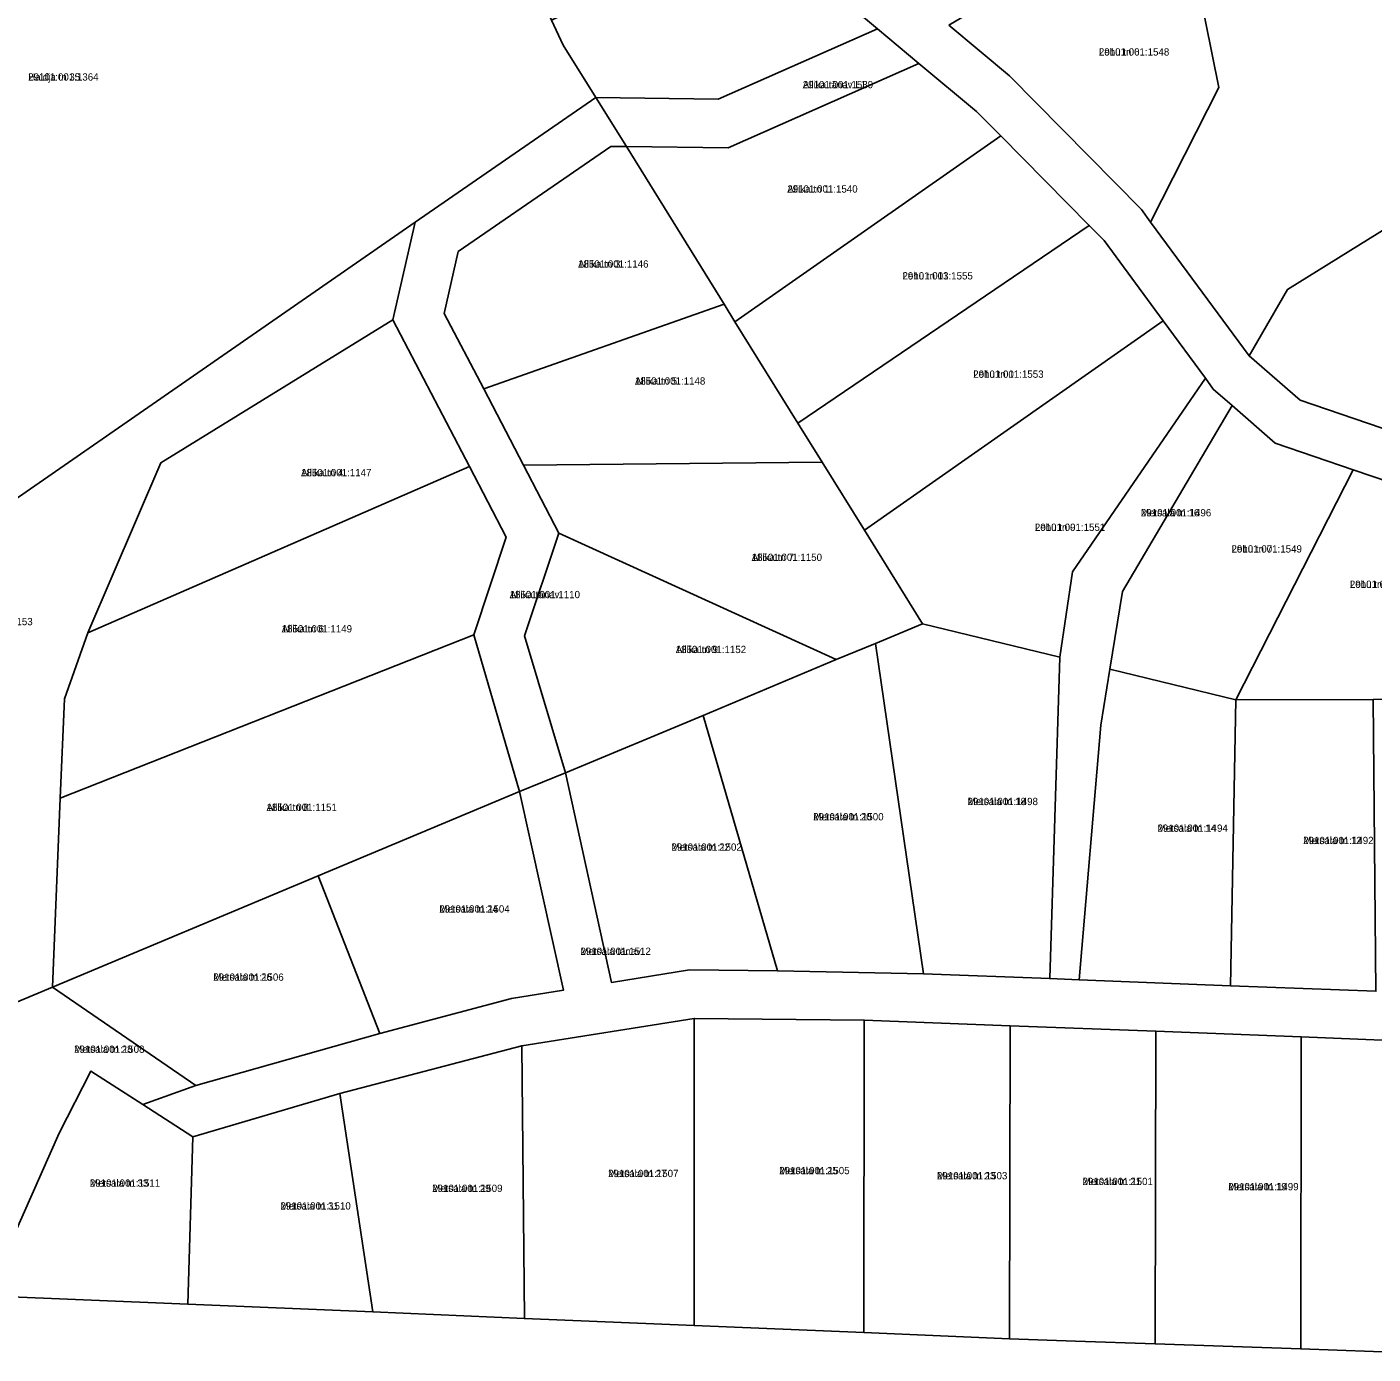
# Model space of a CAD drawing. Extents: x 660838 to 697091, y 6455678 to 6479886.
# Drawn here: x 664567.5 to 664844.9, y 6467484.5 to 6467758.1 of the extents above; entities that cross this region are included whole.
import ezdxf

# ---------------------------------------------------------------- set-up
doc = ezdxf.new("R2010")
doc.units = 0
for name, color, linetype in [('L_AADRESS', 7, 'Continuous'), ('PIIR', 7, 'Continuous'), ('TUNNUS', 7, 'Continuous')]:
    doc.layers.add(name, color=color, linetype=linetype)

msp = doc.modelspace()

# ---------------------------------------------------------------- linework, layer by layer
at = {"layer": 'PIIR'}
for points in [[(664619.34, 6467866.33), (664624.4, 6467868.22), (664630.66, 6467854.99), (664649.11, 6467815.91), (664657.57, 6467797.79), (664675.64, 6467759.51), (664678.05, 6467754.38), (664684.75, 6467743.56), (664647.54, 6467717.86), (664514.87, 6467625.93), (664481.41, 6467691.32), (664477.79, 6467698.39), (664474.15, 6467705.43), (664440.02, 6467772.59), (664457.91, 6467781.88), (664480.66, 6467793.7), (664503.48, 6467805.49), (664530.83, 6467819.65), (664552.51, 6467830.88), (664575.16, 6467842.71), (664617.32, 6467864.54)], [(664842.36, 6467851.27), (664867.78, 6467863.95), (664869.83, 6467846.19), (664877, 6467822.84), (664860.47, 6467801.99), (664847.14, 6467779.64), (664853.5, 6467754.14), (664860.79, 6467724.82), (664827.31, 6467704.02), (664819.37, 6467690.3), (664799.08, 6467717.91), (664813.14, 6467745.61), (664804.89, 6467786.54), (664808.03, 6467816.03), (664815.87, 6467838.1)], [(664757.47, 6467758.52), (664804.89, 6467786.54), (664813.14, 6467745.61), (664799.08, 6467717.91), (664797.22, 6467720.47), (664770, 6467748.08)], [(664675.64, 6467759.51), (664715.03, 6467778.23), (664735.74, 6467763.68), (664742.76, 6467757.76), (664709.94, 6467743.24), (664684.75, 6467743.56), (664678.05, 6467754.38)], [(664709.94, 6467743.24), (664742.76, 6467757.76), (664751.34, 6467750.6), (664711.99, 6467733.21), (664691.05, 6467733.46), (664684.75, 6467743.56)], [(664711.99, 6467733.21), (664751.34, 6467750.6), (664763.2, 6467740.7), (664768.19, 6467735.68), (664713.42, 6467697.35), (664711.2, 6467700.98), (664691.05, 6467733.46)], [(664647.54, 6467717.86), (664684.75, 6467743.56), (664691.05, 6467733.46), (664687.83, 6467733.51), (664656.41, 6467711.8), (664653.51, 6467699.08), (664661.64, 6467683.5), (664669.82, 6467667.8), (664677.15, 6467653.76), (664670.07, 6467632.61), (664678.48, 6467604.32), (664669.05, 6467600.48), (664659.59, 6467632.77), (664666.28, 6467652.95), (664658.71, 6467667.49), (664642.94, 6467697.77)], [(664713.42, 6467697.35), (664768.19, 6467735.68), (664786.42, 6467717.22), (664726.38, 6467676.47)], [(664656.41, 6467711.8), (664687.83, 6467733.51), (664691.05, 6467733.46), (664711.2, 6467700.98), (664661.64, 6467683.5), (664653.51, 6467699.08)], [(664829.88, 6467681.16), (664819.37, 6467690.3), (664827.31, 6467704.02), (664860.79, 6467724.82), (664875.61, 6467697.26), (664888.65, 6467672.94), (664889.91, 6467670.66), (664884.33, 6467671.17), (664887.16, 6467665.73), (664866.07, 6467668.81)], [(664514.87, 6467625.93), (664647.54, 6467717.86), (664642.94, 6467697.77), (664595.08, 6467668.29), (664580.08, 6467633.23), (664575.25, 6467619.58), (664574.4, 6467599.12), (664572.78, 6467560.2), (664552.54, 6467551.71)], [(664726.38, 6467676.47), (664786.42, 6467717.22), (664789.5, 6467714.09), (664801.63, 6467697.52), (664740.1, 6467654.38), (664731.4, 6467668.38)], [(664661.64, 6467683.5), (664711.2, 6467700.98), (664713.42, 6467697.35), (664726.38, 6467676.47), (664731.4, 6467668.38), (664669.82, 6467667.8)], [(664595.08, 6467668.29), (664642.94, 6467697.77), (664658.71, 6467667.49), (664580.08, 6467633.23)], [(664740.1, 6467654.38), (664801.63, 6467697.52), (664810.36, 6467685.72), (664783.01, 6467645.76), (664780.36, 6467628.21), (664752.07, 6467635.08)], [(664783.01, 6467645.76), (664810.36, 6467685.72), (664811.98, 6467683.48), (664815.86, 6467680.1), (664793.3, 6467641.76), (664790.69, 6467625.73), (664788.83, 6467614.18), (664784.37, 6467561.7), (664778.28, 6467561.92), (664780.36, 6467628.21)], [(664793.3, 6467641.76), (664815.86, 6467680.1), (664824.76, 6467672.34), (664840.82, 6467666.85), (664816.61, 6467619.42), (664790.69, 6467625.73)], [(664580.08, 6467633.23), (664658.71, 6467667.49), (664666.28, 6467652.95), (664659.59, 6467632.77), (664574.4, 6467599.12), (664575.25, 6467619.58)], [(664669.82, 6467667.8), (664731.4, 6467668.38), (664740.1, 6467654.38), (664752.07, 6467635.08), (664742.36, 6467631.01), (664734.26, 6467627.69), (664677.15, 6467653.76)], [(664816.61, 6467619.42), (664840.82, 6467666.85), (664863.68, 6467659.07), (664862.83, 6467619.55), (664844.92, 6467619.44)], [(664677.15, 6467653.76), (664734.26, 6467627.69), (664706.85, 6467616.2), (664678.48, 6467604.32), (664670.07, 6467632.61)], [(664742.36, 6467631.01), (664752.07, 6467635.08), (664780.36, 6467628.21), (664778.28, 6467561.92), (664752.25, 6467562.92)], [(664574.4, 6467599.12), (664659.59, 6467632.77), (664669.05, 6467600.48), (664627.51, 6467583.11), (664572.78, 6467560.2)], [(664734.26, 6467627.69), (664742.36, 6467631.01), (664752.25, 6467562.92), (664722.18, 6467563.54), (664706.85, 6467616.2)], [(664788.83, 6467614.18), (664790.69, 6467625.73), (664816.61, 6467619.42), (664815.52, 6467560.47), (664784.37, 6467561.7)], [(664815.52, 6467560.47), (664816.61, 6467619.42), (664844.92, 6467619.44), (664845.51, 6467559.31)], [(664687.95, 6467561.16), (664678.48, 6467604.32), (664706.85, 6467616.2), (664722.18, 6467563.54), (664704.03, 6467563.73)], [(664627.51, 6467583.11), (664669.05, 6467600.48), (664678.06, 6467559.53), (664667.34, 6467557.83), (664640.26, 6467550.63)], [(664572.78, 6467560.2), (664627.51, 6467583.11), (664640.26, 6467550.63), (664602.35, 6467539.87)], [(664552.54, 6467551.71), (664572.78, 6467560.2), (664602.35, 6467539.87), (664591.41, 6467535.98), (664580.7, 6467542.85), (664574.13, 6467530.09), (664559.27, 6467496.52), (664552.12, 6467496.78)], [(664669.53, 6467548.06), (664705.02, 6467553.73), (664705.02, 6467490.38), (664670.03, 6467491.84)], [(664705.02, 6467553.73), (664740.06, 6467553.37), (664740, 6467488.95), (664705.02, 6467490.38)], [(664740, 6467488.95), (664740.06, 6467553.37), (664770.11, 6467552.2), (664769.97, 6467487.69)], [(664770.11, 6467552.2), (664800.13, 6467551.07), (664800.01, 6467486.61), (664783.58, 6467487.15), (664769.97, 6467487.69)], [(664800.01, 6467486.61), (664800.13, 6467551.07), (664830.13, 6467549.9), (664830.01, 6467485.58)], [(664632, 6467538.25), (664669.53, 6467548.06), (664670.03, 6467491.84), (664638.82, 6467493.22)], [(664830.13, 6467549.9), (664860.11, 6467548.72), (664860, 6467484.52), (664830.01, 6467485.58)], [(664591.41, 6467535.98), (664601.69, 6467529.31), (664600.69, 6467494.8), (664559.27, 6467496.52), (664574.13, 6467530.09), (664580.7, 6467542.85)], [(664601.69, 6467529.31), (664632, 6467538.25), (664638.82, 6467493.22), (664600.69, 6467494.8)]]:
    msp.add_lwpolyline(points, close=True, dxfattribs=at)
for points in [[(664863.68, 6467659.07), (664840.82, 6467666.85), (664824.76, 6467672.34), (664815.86, 6467680.1), (664811.98, 6467683.48), (664810.36, 6467685.72), (664801.63, 6467697.52), (664789.5, 6467714.09), (664786.42, 6467717.22), (664768.19, 6467735.68), (664763.2, 6467740.7), (664751.34, 6467750.6), (664742.76, 6467757.76), (664735.74, 6467763.68)], [(664757.47, 6467758.52), (664770, 6467748.08), (664797.22, 6467720.47), (664799.08, 6467717.91), (664819.37, 6467690.3), (664829.88, 6467681.16), (664866.07, 6467668.81)], [(664860.11, 6467548.72), (664830.13, 6467549.9), (664800.13, 6467551.07), (664770.11, 6467552.2), (664740.06, 6467553.37), (664705.02, 6467553.73), (664669.53, 6467548.06), (664632, 6467538.25), (664601.69, 6467529.31), (664591.41, 6467535.98), (664602.35, 6467539.87), (664640.26, 6467550.63), (664667.34, 6467557.83), (664678.06, 6467559.53), (664669.05, 6467600.48), (664678.48, 6467604.32), (664687.95, 6467561.16), (664704.03, 6467563.73), (664722.18, 6467563.54), (664752.25, 6467562.92), (664778.28, 6467561.92), (664784.37, 6467561.7), (664815.52, 6467560.47), (664845.51, 6467559.31)], [(664559.27, 6467496.52), (664600.69, 6467494.8), (664638.82, 6467493.22), (664670.03, 6467491.84), (664705.02, 6467490.38), (664740, 6467488.95), (664769.97, 6467487.69), (664783.58, 6467487.15), (664800.01, 6467486.61), (664830.01, 6467485.58), (664860, 6467484.52)]]:
    msp.add_lwpolyline(points, dxfattribs=at)

# ---------------------------------------------------------------- texts
at = {"layer": 'L_AADRESS'}
for s, p in [('Lohu tn 6', (664788.42, 6467752.23)), ('Haldja tn 35', (664567.78, 6467747.07)), ('Allika tänav L1', (664727.39, 6467745.49)), ('Allika tn 1', (664724.2, 6467723.98)), ('Allika tn 3', (664681.1, 6467708.51)), ('Lohu tn 13', (664747.94, 6467706.07)), ('Lohu tn 11', (664762.52, 6467685.8)), ('Allika tn 5', (664692.81, 6467684.39)), ('Allika tn 4', (664624.01, 6467665.5)), ('Metsala tn 16', (664797.07, 6467657.23)), ('Lohu tn 9', (664775.23, 6467654.23)), ('Lohu tn 7', (664815.75, 6467649.77)), ('Allika tn 7', (664716.86, 6467648.04)), ('Lohu tn 5', (664840.14, 6467642.48)), ('Allika tänav', (664666.99, 6467640.36)), ('Allika tn 6', (664620.01, 6467633.3)), ('Allika tn 9', (664701.22, 6467629.04)), ('Allika tn 8', (664616.89, 6467596.49)), ('Metsala tn 18', (664761.36, 6467597.7)), ('Metsala tn 20', (664729.55, 6467594.55)), ('Metsala tn 14', (664800.49, 6467592.2)), ('Metsala tn 22', (664700.33, 6467588.3)), ('Metsala tn 12', (664830.52, 6467589.66)), ('Metsala tn 24', (664652.5, 6467575.55)), ('Metsala tänav', (664681.58, 6467566.82)), ('Metsala tn 26', (664605.93, 6467561.49)), ('Metsala tn 28', (664577.23, 6467546.63)), ('Metsala tn 25', (664722.54, 6467521.61)), ('Metsala tn 33', (664580.48, 6467519.03)), ('Metsala tn 27', (664687.28, 6467521.01)), ('Metsala tn 23', (664755.05, 6467520.55)), ('Metsala tn 21', (664785.05, 6467519.37)), ('Metsala tn 29', (664651.02, 6467517.95)), ('Metsala tn 19', (664815.07, 6467518.29)), ('Metsala tn 31', (664619.75, 6467514.32))]:
    msp.add_text(s, height=1.5, dxfattribs=at).set_placement(p)
at = {"layer": 'TUNNUS'}
for s, p in [('29101:001:1548', (664788.42, 6467752.23)), ('29101:001:1364', (664567.78, 6467747.07)), ('29101:001:1539', (664727.39, 6467745.49)), ('29101:001:1540', (664724.2, 6467723.98)), ('18501:001:1146', (664681.1, 6467708.51)), ('29101:001:1555', (664747.94, 6467706.07)), ('29101:001:1553', (664762.52, 6467685.8)), ('18501:001:1148', (664692.81, 6467684.39)), ('18501:001:1147', (664624.01, 6467665.5)), ('29101:001:1496', (664797.07, 6467657.23)), ('29101:001:1551', (664775.23, 6467654.23)), ('29101:001:1549', (664815.75, 6467649.77)), ('18501:001:1150', (664716.86, 6467648.04)), ('29101:001:1547', (664840.14, 6467642.48)), ('18501:001:1110', (664666.99, 6467640.36)), ('18501:001:1153', (664554.2, 6467634.79)), ('18501:001:1149', (664620.01, 6467633.3)), ('18501:001:1152', (664701.22, 6467629.04)), ('18501:001:1151', (664616.89, 6467596.49)), ('29101:001:1498', (664761.36, 6467597.7)), ('29101:001:1500', (664729.55, 6467594.55)), ('29101:001:1494', (664800.49, 6467592.2)), ('29101:001:1502', (664700.33, 6467588.3)), ('29101:001:1492', (664830.52, 6467589.66)), ('29101:001:1504', (664652.5, 6467575.55)), ('29101:001:1512', (664681.58, 6467566.82)), ('29101:001:1506', (664605.93, 6467561.49)), ('29101:001:1508', (664577.23, 6467546.63)), ('29101:001:1505', (664722.54, 6467521.61)), ('29101:001:1511', (664580.48, 6467519.03)), ('29101:001:1507', (664687.28, 6467521.01)), ('29101:001:1503', (664755.05, 6467520.55)), ('29101:001:1501', (664785.05, 6467519.37)), ('29101:001:1509', (664651.02, 6467517.95)), ('29101:001:1499', (664815.07, 6467518.29)), ('29101:001:1510', (664619.75, 6467514.32))]:
    msp.add_text(s, height=1.5, dxfattribs=at).set_placement(p)

doc.saveas('drawing.dxf')
